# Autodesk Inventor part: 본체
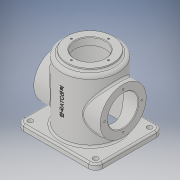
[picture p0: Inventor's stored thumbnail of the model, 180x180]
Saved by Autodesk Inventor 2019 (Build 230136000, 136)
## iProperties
Created: 2020-12
Part Number: 본체
Material: 일반
Document SubType Name: Modeling
Designer: jun-1-19
Density: 1 g/cm^3
Appearance: 기본값
Author: jun-1-19
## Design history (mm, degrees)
sketch "스케치1"
  geometry: L1 (70, -60)-(-70, -60); L2 (-70, -60)-(-70, 60); L3 (-70, 60)-(70, 60); L4 (70, 60)-(70, -60); L5 (70, -60)-(-70, 60); L6 (-70, -60)-(70, 60); 1 further point
  constraints: 12 end point, 2 midpoint, 2 parallel, 1 horizontal, 1 perpendicular
  dimensions: "d0" = 140 distance of L2.end L3.end; "d1" = 120 distance of L1.end L2.end
extrude "돌출1" new body sketch "스케치1" distance "d2" = 10; taper "d3" = 0 deg
sketch "스케치2"
  geometry: C1 r 50 at (0, 0); 1 further point
  constraints: 1 centre point, 1 coincident
  dimensions: "d4" = 100 diameter of C1
extrude "돌출2" join sketch "스케치2" distance "d5" = 110; taper "d6" = 0 deg
sketch "스케치4"
  geometry: C1 r 41 at (0, 0); 1 further point
  constraints: 1 centre point, 1 coincident
  dimensions: "d8" = 82 diameter of C1
extrude "돌출3" join sketch "스케치4" distance "d9" = 5; taper "d10" = 0 deg
sketch "스케치5"
  geometry: 3 further points
  constraints: 2 coincident
hole "구멍1" sketch "스케치5" at (0, 0) diameter "d11" = 54; stored, may be unused: countersink angle "d15" = 90 deg, drill point angle "d17" = 0 deg; dims "d12" = 18, "d13" = 84, "d14" = 112, "d16" = 23
node "작업 평면4"
sketch "스케치6"
  geometry: L1 (0, -60)-(0, 60) reference; C1 r 41 at (60, 0); 2 further points
  constraints: 1 centre point, 1 horizontal alignment, 1 midpoint
  dimensions: "d19" = 82 diameter of C1; "d20" = 60 distance from line of L1 C1.centre
extrude "돌출4" join sketch "스케치6" stored distance "d21" = 5; taper "d22" = 0 deg
sketch "스케치7"
  geometry: C1 r 41 at (0, 0) reference; 2 further points
  constraints: 1 coincident
hole "구멍2" sketch "스케치7" at (0, 0) diameter "d23" = 54; stored, may be unused: countersink angle "d27" = 90 deg, drill point angle "d29" = 0 deg; dims "d24" = 18, "d25" = 84, "d26" = 112, "d28" = 23
fillet "모깎기1" dims "d30" = 12
sketch "스케치8"
  geometry: A1 r 12 centre (58, -48) between (58, -60) and (70, -48) reference; 2 further points
  constraints: 1 coincident
hole "구멍3" sketch "스케치8" at (58, -48) diameter "d31" = 9; stored, may be unused: countersink angle "d35" = 90 deg, drill point angle "d37" = 0 deg; dims "d32" = 18, "d33" = 84, "d34" = 112, "d36" = 23
fillet "모깎기2" dims "d38" = 3
sketch "스케치9"
  geometry: 2 further points
  constraints: 1 vertical alignment
  dimensions: "d39" = 33 distance of point (0, 0) point (0, 33)
hole "구멍4" sketch "스케치9" at (0, 33) diameter "d40" = 3.242; stored, may be unused: countersink angle "d44" = 90 deg, drill point angle "d46" = 118 deg; dims "d41" = 8, "d42" = 84, "d43" = 112, "d45" = 10
sketch "스케치10"
  geometry: L1 (48, -60)-(-48, -60) reference; C1 r 41 at (0, 0) reference; 3 further points
  constraints: 1 midpoint, 1 vertical alignment
  dimensions: "d50" = 33 distance of C1.centre point (0, 33)
hole "구멍5" sketch "스케치10" at (0, 33) diameter "d51" = 3.242; stored, may be unused: countersink angle "d55" = 90 deg, drill point angle "d57" = 118 deg; dims "d52" = 8, "d53" = 84, "d54" = 112, "d56" = 10
fillet "모깎기3" dims "d61" = 3
chamfer "모따기1" distance "d62" = 1; stored, may be unused: second distance "d63" = 2, angle "d64" = 45 deg
chamfer "모따기2" distance "d65" = 1; stored, may be unused: second distance "d66" = 2, angle "d67" = 45 deg
node "작업 평면5"
sketch "스케치11"
  geometry: L1 (58, -10)-(-58, -10) reference; 3 further points
  constraints: 1 midpoint, 1 vertical alignment, 1 other
  dimensions: "d68" = 70 distance from line of L1 point (0, 60)
feature "엠보싱1" sketch "스케치11" dims "d0" = 140, "d1" = 120, "d13" = 84, "d69" = 0.5, "d70" = 0
fillet "모깎기4" dims "d71" = 6
fillet "모깎기5" dims "d72" = 3
node "솔리드1"
mirror "미러1"
mirror "미러2"
mirror "미러3"
pattern_circular "원형 패턴1" dims angle "d48" = 360 deg
pattern_circular "원형 패턴2" dims angle "d59" = 360 deg
mirror "미러4"
other parameters: "d18" = 59
